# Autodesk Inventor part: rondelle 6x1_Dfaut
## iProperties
Created: 2006-03
Part Number: rondelle 6x1_Dfaut
Document SubType Name: Modeling
Designer: Flavien MARTY
Author: Flavien MARTY
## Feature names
1. Base1
